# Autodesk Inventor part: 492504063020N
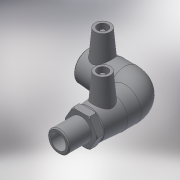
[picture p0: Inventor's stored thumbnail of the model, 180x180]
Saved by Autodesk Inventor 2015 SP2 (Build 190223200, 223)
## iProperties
Created: 2017-06
Part Number: 492504063020N
Material: Generic
Description: PLASSON 90° ELBOW MALE TRANSITION 63 x 2"
Document SubType Name: Modeling
Designer: KIM
Mass: 566.987 g
Surface Area: 1081.46 cm^2
Volume: 566.987 cm^3
Density: 1 g/cm^3
Appearance: Default
Author: KIM
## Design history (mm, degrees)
derived "492504.ipt"
feature "Solid1::492504.ipt"
tag "TaggingFeature1"
body "Solid1"
other parameters: "d2" = 82, "d4" = 44, "d5" = 73.8, "d8" = 168 deg, "d10" = 23.2, "d11" = 7.73333, "d29" = 57, "d30" = 15, "d31" = 72.6, "d34" = 5 deg, "d41" = 4, "d42" = 14, "d43" = 0, "d48" = 91, "d49" = 63, "d50" = 53.55, "d51" = 23.2, "d52" = 58, "d54" = 90 deg, "d57" = 63, "d58" = 58, "d59" = 0, "d61" = 90 deg, "d86" = 3, "d87" = 0, "d93" = 0.1, "d94" = 17, "d95" = 59.614, "d96" = 41.7298, "d97" = 47, "d98" = 68, "d99" = 82, "d100" = 61.2, "d102" = 1.26, "d106" = 0, "d_" = 63, "L_1" = 58, "D_" = 47, "A_" = 57, "d_2" = 12, "L_2" = 68, "D_1" = 82, "R_" = 59.614
